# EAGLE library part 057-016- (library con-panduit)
CONNECTOR 10-pin series 057 contact pc board low profile headers
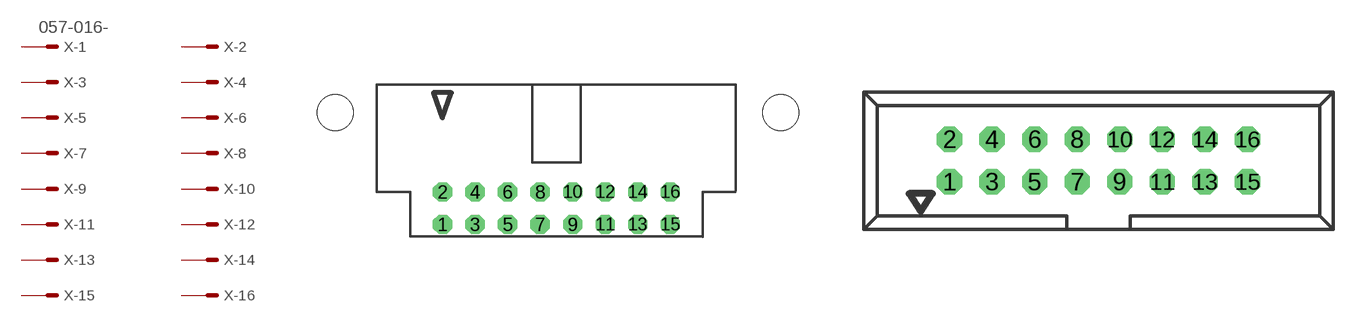
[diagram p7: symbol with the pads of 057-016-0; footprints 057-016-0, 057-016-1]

Designator prefix X; gates -1=MV -2=M -3=M -4=M -5=M -6=M -7=M -8=M -9=M -10=M -11=M -12=M -13=M -14=M -15=M -16=M

## 057-016-0 (OC_FARNELL: unknown; OC_NEWARK: unknown)  [057-016-0]
1  -1:S  pas
2  -2:S  pas
3  -3:S  pas
4  -4:S  pas
5  -5:S  pas
6  -6:S  pas
7  -7:S  pas
8  -8:S  pas
9  -9:S  pas
10  -10:S  pas
11  -11:S  pas
12  -12:S  pas
13  -13:S  pas
14  -14:S  pas
15  -15:S  pas
16  -16:S  pas

## 057-016-1 (OC_FARNELL: unknown; OC_NEWARK: unknown)  [057-016-1]
Pads as for 057-016-0

## Footprint 057-016-0 (pad centres in mm)
CONNECTOR series 057 contact pc board low profile headers angled
drill 1 octagon: 1 -8.89,-5.08; 2 -8.89,-2.54; 3 -6.35,-5.08; 4 -6.35,-2.54; 5 -3.81,-5.08; 6 -3.81,-2.54; 7 -1.27,-5.08; 8 -1.27,-2.54; 9 1.27,-5.08; 10 1.27,-2.54; 11 3.81,-5.08; 12 3.81,-2.54; 13 6.35,-5.08; 14 6.35,-2.54; 15 8.89,-5.08; 16 8.89,-2.54
hole 2.8 at -17.29,3.66
hole 2.8 at 17.54,3.66

## Footprint 057-016-1 (pad centres in mm)
CONNECTOR series 057 contact pc board low profile headers straight
drill 1 octagon: 1 -8.89,-1.27; 2 -8.89,1.27; 3 -6.35,-1.27; 4 -6.35,1.27; 5 -3.81,-1.27; 6 -3.81,1.27; 7 -1.27,-1.27; 8 -1.27,1.27; 9 1.27,-1.27; 10 1.27,1.27; 11 3.81,-1.27; 12 3.81,1.27; 13 6.35,-1.27; 14 6.35,1.27; 15 8.89,-1.27; 16 8.89,1.27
